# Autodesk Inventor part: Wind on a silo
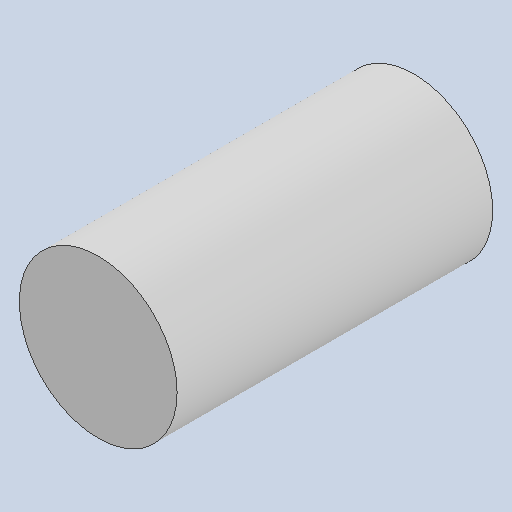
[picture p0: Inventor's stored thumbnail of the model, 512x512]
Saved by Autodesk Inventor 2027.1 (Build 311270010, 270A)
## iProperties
Created: 2026-10
Part Number: Wind on a silo
Material: Generic
Document SubType Name: Modeling
Designer: niels
Density: 1 g/cm^3
Appearance: Default
Author: niels
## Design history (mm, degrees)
sketch "Sketch1"
  geometry: C1 r 1500 at (0, 0)
  constraints: 1 centre point
  dimensions: "d0" = 6000 dimension on C1.centre C1
extrude "Extrusion1" new body sketch "Sketch1" distance "d0" = 6000; taper "d1" = 0 deg
node "Silo"
